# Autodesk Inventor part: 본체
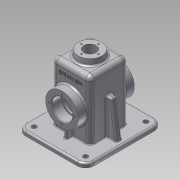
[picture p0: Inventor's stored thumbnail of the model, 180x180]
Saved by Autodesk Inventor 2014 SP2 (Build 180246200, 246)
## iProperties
Created: 2016-08
Part Number: 본체
Material: 알루미늄 6061
Document SubType Name: Modeling
Designer: user
Density: 2.71 g/cm^3
Appearance: 알루미늄 - 평지
Mass: 796.093 g
Surface Area: 911.214 cm^2
Volume: 293.761 cm^3
Author: user
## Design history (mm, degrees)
sketch "스케치2"
  geometry: L1 (-52.5, -60)-(52.5, -60); L2 (52.5, -60)-(52.5, 60); L3 (52.5, 60)-(-52.5, 60); L4 (-52.5, 60)-(-52.5, -60); L5 (-52.5, -60)-(52.5, 60); L6 (52.5, -60)-(-52.5, 60); 3 further points
  constraints: 12 end point, 3 midpoint, 2 parallel, 1 coincident, 1 horizontal, 1 perpendicular
  dimensions: "d4" = 120 distance of L3.end L1.start; "d5" = 105 distance of L2.end L3.end
extrude "돌출2" new body sketch "스케치2" distance "d6" = 3; taper "d7" = 0 deg
sketch "스케치3"
  geometry: L1 (-57.5, 65)-(57.5, 65); L2 (57.5, 65)-(57.5, -65); L3 (57.5, -65)-(-57.5, -65); L4 (-57.5, -65)-(-57.5, 65); L5 (-57.5, 65)-(57.5, -65); L6 (57.5, 65)-(-57.5, -65); 3 further points
  constraints: 12 end point, 3 midpoint, 2 parallel, 1 coincident, 1 horizontal, 1 perpendicular
  dimensions: "d8" = 115 distance of L1.start L1.end; "d9" = 130 distance of L1.end L2.end
extrude "돌출3" join sketch "스케치3" distance "d10" = 7; taper "d11" = 0 deg
sketch "스케치4"
  geometry: L1 (32.5, 32.5)-(-32.5, 32.5); L2 (-32.5, 32.5)-(-32.5, -32.5); L3 (-32.5, -32.5)-(32.5, -32.5); L4 (32.5, -32.5)-(32.5, 32.5); L5 (32.5, 32.5)-(-32.5, -32.5); L6 (-32.5, 32.5)-(32.5, -32.5); 3 further points
  constraints: 12 end point, 3 midpoint, 2 parallel, 2 perpendicular, 1 coincident, 1 horizontal
  dimensions: "d12" = 65 distance of L3.end L1.start
extrude "돌출4" join sketch "스케치4" distance "d13" = 100; taper "d14" = 0 deg
fillet "모깎기1" dims "d15" = 8
fillet "모깎기2" dims "d16" = 8
feature "쉘1" dims "d17" = 5
sketch "스케치5"
  geometry: L1 (95, 0)-(0, 0) reference; L2 (95, 110)-(95, 0) reference; L3 (0, 110)-(95, 110) reference; L4 (0, 0)-(0, 110) reference; L5 (20, 79.5)-(20, 30.5) reference; L6 (72, 82.5)-(23, 82.5) reference; L7 (75, 30.5)-(75, 79.5) reference; L8 (23, 27.5)-(72, 27.5) reference; A1 r 3 centre (23, 79.5) between (23, 82.5) and (20, 79.5) reference; A2 r 3 centre (72, 79.5) between (75, 79.5) and (72, 82.5) reference; A3 r 3 centre (72, 30.5) between (72, 27.5) and (75, 30.5) reference; A4 r 3 centre (23, 30.5) between (20, 30.5) and (23, 27.5) reference; 1 further point
extrude "돌출5" join sketch "스케치5" stored distance "d18" = 100; taper "d19" = 0 deg
sketch "스케치6"
  geometry: L1 (77, 10)-(-28, 10) reference; C1 r 27.5 at (24.5, -45); 2 further points
  constraints: 1 centre point, 1 midpoint, 1 vertical alignment
  dimensions: "d20" = 55 diameter of C1; "d21" = 55 distance from line of L1 C1.centre
extrude "돌출6" join sketch "스케치6" distance "d22" = 15; taper "d23" = 0 deg
sketch "스케치8"
  geometry: L1 (47.5, 55)-(47.5, 72.5); L2 (47.5, 72.5)-(30.5, 72.5); L3 (30.5, 72.5)-(30.5, 70); L4 (30.5, 70)-(-30.5, 70); L5 (-30.5, 70)-(-30.5, 72.5); L6 (-30.5, 72.5)-(-47.5, 72.5); L7 (-47.5, 72.5)-(-47.5, 55); L8 (-47.5, 55)-(47.5, 55); L9 (47.5, 27.5)-(47.5, 82.5) reference; L10 (-47.5, 27.5)-(-47.5, 82.5) reference; 1 further point
  constraints: 16 end point, 4 collinear, 4 parallel, 2 vertical, 1 perpendicular
  dimensions: "d27" = 17 distance of L1.end L2.end; "d28" = 35 diameter of L2 L8; "d29" = 30 diameter of L4 L8; "d30" = 55 vertical distance of point (0, 0) L1.start; "d31" = 35 diameter of L6 L8
revolve "회전1" sketch "스케치8" stored, may be unused: angle "d32" = 90 deg
sketch "스케치9"
  geometry: L1 (-32.5, 102)-(-32.5, 10) reference; L2 (-57.5, 10)-(57.5, 10) reference; L3 (-49.5, 10)-(-41.068, 70); L4 (-57.5, 3)-(-57.5, 10) reference; L5 (-41.068, 70)-(-32.5, 70); L6 (52.5, 0)-(-52.5, 0) reference; 1 further point
  constraints: 4 end point, 2 point on line, 1 perpendicular
  dimensions: "d42" = 8 distance of L2.start L3.start; "d43" = 8 deg angle of L4 L3; "d130" = 70 distance between parallel lines of L6 L5
feature "리브1" sketch "스케치9" dims "d45" = 1, "d46" = 10, "d47" = 0, "d48" = 0, "d49" = 1, "d50" = 1
fillet "모깎기3" dims "d51" = 9
hole "구멍2" diameter "d54" = 8; stored, may be unused: countersink angle "d58" = 90 deg, drill point angle "d60" = 0 deg; dims "d52" = 10, "d53" = 10, "d55" = 6, "d56" = 4, "d57" = 2, "d59" = 8
sketch "스케치11" dims "d67" = 42
  geometry: C1 r 27.5 at (0, 0) reference; 3 further points
  constraints: 2 vertical alignment, 1 coincident, 2 other
hole "구멍3" sketch "스케치11" at (0, -21) diameter "d68" = 3.242; stored, may be unused: countersink angle "d72" = 90 deg, drill point angle "d74" = 118 deg; dims "d69" = 8, "d70" = 4, "d71" = 2, "d73" = 10
sketch "스케치12" dims "d75" = 42
  geometry: C1 r 27.5 at (0, 0) reference; 3 further points
  constraints: 2 vertical alignment, 1 coincident, 2 other
hole "구멍4" sketch "스케치12" at (0, 21) diameter "d76" = 3.242; stored, may be unused: countersink angle "d80" = 90 deg, drill point angle "d82" = 118 deg; dims "d77" = 8, "d78" = 4, "d79" = 2, "d81" = 10
sketch "스케치14"
  geometry: L1 (-8, 0)-(-8, -92) reference; L2 (5.728, 18)-(43.272, 18) reference; 2 further points
  constraints: 1 other
  dimensions: "d100" = 32.5 distance from line of L1 point (24.5, -8); "d101" = 26 distance from line of L2 point (24.5, -8)
feature "엠보싱1" sketch "스케치14" dims "d102" = 0.5, "d103" = 0
fillet "모깎기4" dims "d104" = 14
fillet "모깎기5" dims "d105" = 3
fillet "모깎기6" dims "d106" = 3
fillet "모깎기7" dims "d107" = 3
fillet "모깎기8" dims "d108" = 3
fillet "모깎기9" dims "d109" = 3
chamfer "모따기1" distance "d113" = 1; stored, may be unused: second distance "d114" = 2, angle "d115" = 45 deg
sketch "스케치15"
  geometry: L1 (-47.5, 27.5)-(-32.5, 27.5) reference; L2 (-32.5, 10)-(-32.5, 42.51) reference; L3 (-51, 10)-(51, 10) reference; L4 (-42.5, 27.5)-(-42.5, 10); L5 (-27.5, 102)-(-27.5, 0) reference; 1 further point
  constraints: 2 end point, 2 point on line, 1 perpendicular
  dimensions: "d116" = 15 distance between parallel lines of L5 L4
feature "리브2" sketch "스케치15" dims "d117" = 1, "d118" = 6, "d119" = 0, "d120" = 0, "d121" = 1, "d122" = 1
fillet "모깎기13" dims "d123" = 3
fillet "모깎기14" dims "d124" = 3
fillet "모깎기15" dims "d125" = 1
fillet "모깎기16" dims "d129" = 0.3
node "작업 평면1"
sketch "스케치16"
  geometry: C1 r 20 at (0, 0); 1 further point
  constraints: 1 centre point, 1 coincident
  dimensions: "d132" = 40 diameter of C1
extrude "돌출8" join sketch "스케치16" stored distance "d133" = 10; taper "d134" = 7 deg
hole "구멍6" diameter "d137" = 21; stored, may be unused: countersink angle "d141" = 90 deg, drill point angle "d143" = 0 deg; dims "d135" = 10, "d136" = 10, "d138" = 7, "d139" = 4, "d140" = 2, "d142" = 35
sketch "스케치17" dims "d144" = 29
  geometry: C1 r 20 at (0, 0) reference; 3 further points
  constraints: 2 vertical alignment, 1 coincident, 2 other
hole "구멍7" sketch "스케치17" at (0, 14.5) diameter "d145" = 2.459; stored, may be unused: countersink angle "d149" = 90 deg, drill point angle "d151" = 118 deg; dims "d146" = 7, "d147" = 4, "d148" = 2, "d150" = 9
fillet "모깎기17" dims "d155" = 3
node "솔리드2"
mirror "대칭1"
mirror "대칭2"
pattern_linear "직사각형 패턴1" dims "d63" = 102, "d66" = 87
pattern_circular "원형 패턴1" dims angle "d84" = 360 deg
pattern_circular "원형 패턴2" dims angle "d87" = 360 deg
mirror "대칭3"
pattern_circular "원형 패턴4" dims angle "d153" = 360 deg
node "투영된 루프1"
